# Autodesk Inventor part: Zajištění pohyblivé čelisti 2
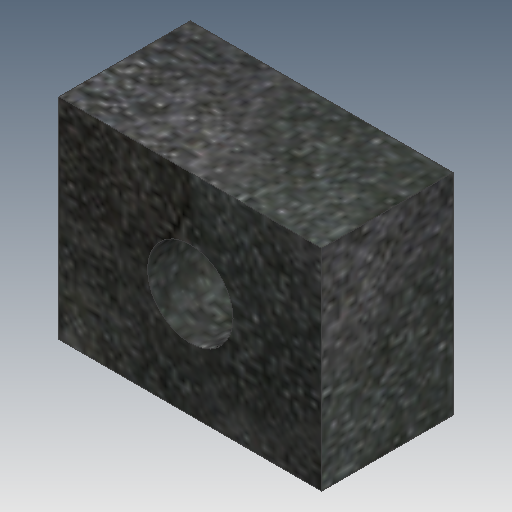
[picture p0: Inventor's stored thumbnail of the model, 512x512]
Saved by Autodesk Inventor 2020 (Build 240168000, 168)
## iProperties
Created: 2025-03
Part Number: Zajištění pohyblivé čelisti 2
Material: Ocel
Document SubType Name: Modeling
Designer: doma
Density: 7.85 g/cm^3
Appearance: Plech
Mass: 180.121 g
Surface Area: 59.9135 cm^2
Volume: 22.9454 cm^3
Author: doma
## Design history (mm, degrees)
sketch "Náčrt1"
  geometry: L1 (-20, -16)-(20, -16); L2 (20, -16)-(20, 16); L3 (20, 16)-(-20, 16); L4 (-20, 16)-(-20, -16); L5 (-20, -16)-(20, 16); L6 (20, -16)-(-20, 16); C1 r 6.5 at (0, 0); 1 further point
  constraints: 12 end point, 2 midpoint, 2 parallel, 1 centre point, 1 coincident, 1 horizontal, 1 perpendicular
  dimensions: "d0" = 40 distance of L3.end L2.end; "d1" = 32 distance of L2.end L1.end; "d4" = 13 diameter of C1
extrude "Vysunutí1" new body sketch "Náčrt1" distance "d2" = 20; taper "d3" = 0 deg
node "Těleso1"
